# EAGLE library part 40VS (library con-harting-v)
CONNECTOR
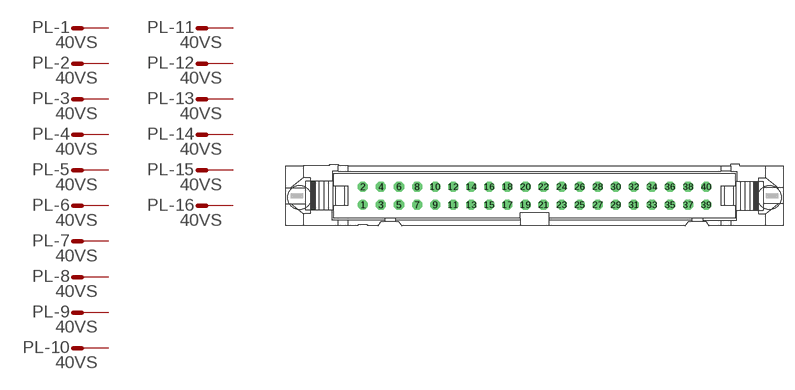
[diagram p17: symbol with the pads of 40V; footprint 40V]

Designator prefix PL; gates -1=M -2=M -3=M -4=M -5=M -6=M -7=M -8=M -9=M -10=M -11=M -12=M -13=M -14=M -15=M -16=M -17=M -18=M -19=M -20=M -21=M -22=M -23=M -24=M -25=M -26=M -27=M -28=M -29=M -30=M -31=M -32=M -33=M -34=M -35=M -36=M -37=M -38=M -39=M -40=M

## 40VS (OC_FARNELL: unknown; OC_NEWARK: unknown)  [40V]
1  -1:S  pas
2  -2:S  pas
3  -3:S  pas
4  -4:S  pas
5  -5:S  pas
6  -6:S  pas
7  -7:S  pas
8  -8:S  pas
9  -9:S  pas
10  -10:S  pas
11  -11:S  pas
12  -12:S  pas
13  -13:S  pas
14  -14:S  pas
15  -15:S  pas
16  -16:S  pas
17  -17:S  pas
18  -18:S  pas
19  -19:S  pas
20  -20:S  pas
21  -21:S  pas
22  -22:S  pas
23  -23:S  pas
24  -24:S  pas
25  -25:S  pas
26  -26:S  pas
27  -27:S  pas
28  -28:S  pas
29  -29:S  pas
30  -30:S  pas
31  -31:S  pas
32  -32:S  pas
33  -33:S  pas
34  -34:S  pas
35  -35:S  pas
36  -36:S  pas
37  -37:S  pas
38  -38:S  pas
39  -39:S  pas
40  -40:S  pas

## Footprint 40V (pad centres in mm)
CONNECTOR
drill 0.914 round: 1 -24.13,-1.27
drill 0.914 octagon: 2 -24.13,1.27; 3 -21.59,-1.27; 4 -21.59,1.27; 5 -19.05,-1.27; 6 -19.05,1.27; 7 -16.51,-1.27; 8 -16.51,1.27; 9 -13.97,-1.27; 10 -13.97,1.27; 11 -11.43,-1.27; 12 -11.43,1.27; 13 -8.89,-1.27; 14 -8.89,1.27; 15 -6.35,-1.27; 16 -6.35,1.27; 17 -3.81,-1.27; 18 -3.81,1.27; 19 -1.27,-1.27; 20 -1.27,1.27; 21 1.27,-1.27; 22 1.27,1.27; 23 3.81,-1.27; 24 3.81,1.27; 25 6.35,-1.27; 26 6.35,1.27; 27 8.89,-1.27; 28 8.89,1.27; 29 11.43,-1.27; 30 11.43,1.27; 31 13.97,-1.27; 32 13.97,1.27; 33 16.51,-1.27; 34 16.51,1.27; 35 19.05,-1.27; 36 19.05,1.27; 37 21.59,-1.27; 38 21.59,1.27; 39 24.13,-1.27; 40 24.13,1.27
hole 3.302 at 33.02,-0.254
hole 3.302 at -33.02,-0.254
